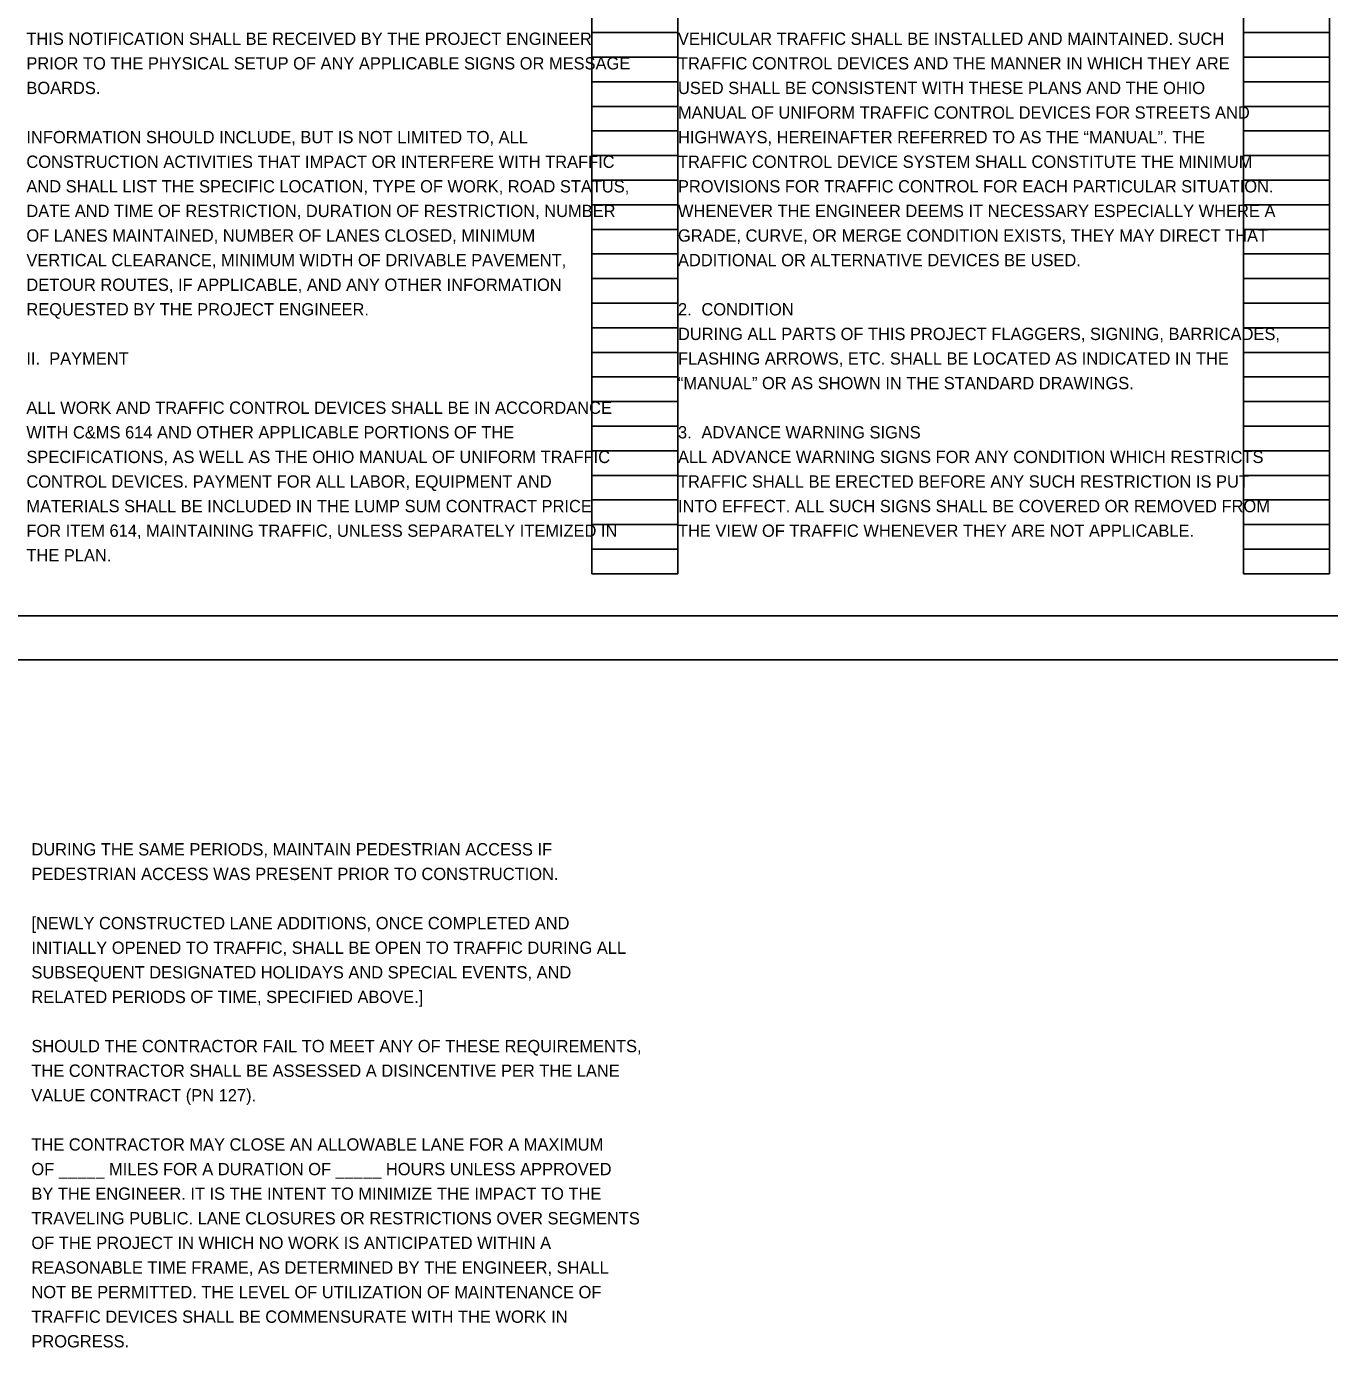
# Model space of a CAD drawing. Extents: x -15.1 to 34, y -7.8 to 43.8.
# Drawn here: x 2.4 to 17.24, y -7.83 to 7.21 of the extents above; entities that cross this region are included whole.
import ezdxf

# ---------------------------------------------------------------- set-up
doc = ezdxf.new("R2010")
doc.units = 0
for name, color, linetype in [('SH_Border', 7, 'Continuous'), ('SH_Cut_Line', 7, 'Continuous'), ('SH_Data', 7, 'Continuous'), ('SH_Text', 7, 'Continuous'), ('SN_X_Public', 7, 'Continuous')]:
    doc.layers.add(name, color=color, linetype=linetype)

msp = doc.modelspace()

# ---------------------------------------------------------------- linework, layer by layer
at = {"layer": 'SH_Border'}
msp.add_lwpolyline([(1.5, 21.5), (33.5, 21.5), (33.5, 0.5), (1.5, 0.5)], close=True, dxfattribs=at)
at = {"layer": 'SH_Cut_Line'}
msp.add_lwpolyline([(0, 0), (34, 0), (34, 22), (0, 22)], close=True, dxfattribs=at)
at = {"layer": 'SH_Data'}
for p, q in [((8.84, 0.98), (8.84, 21.14)), ((9.82, 0.98), (9.82, 21.14)), ((16.26, 0.98), (16.26, 21.14)), ((17.24, 0.98), (17.24, 21.14)), ((8.84, 7.14), (9.82, 7.14)), ((16.26, 7.14), (17.24, 7.14)), ((8.84, 6.86), (9.82, 6.86)), ((16.26, 6.86), (17.24, 6.86)), ((8.84, 6.58), (9.82, 6.58)), ((16.26, 6.58), (17.24, 6.58)), ((8.84, 6.3), (9.82, 6.3)), ((16.26, 6.3), (17.24, 6.3)), ((8.84, 6.02), (9.82, 6.02)), ((16.26, 6.02), (17.24, 6.02)), ((8.84, 5.74), (9.82, 5.74)), ((16.26, 5.74), (17.24, 5.74)), ((8.84, 5.46), (9.82, 5.46)), ((16.26, 5.46), (17.24, 5.46)), ((8.84, 5.18), (9.82, 5.18)), ((16.26, 5.18), (17.24, 5.18)), ((8.84, 4.9), (9.82, 4.9)), ((16.26, 4.9), (17.24, 4.9)), ((8.84, 4.62), (9.82, 4.62)), ((16.26, 4.62), (17.24, 4.62)), ((8.84, 4.34), (9.82, 4.34)), ((16.26, 4.34), (17.24, 4.34)), ((8.84, 4.06), (9.82, 4.06)), ((16.26, 4.06), (17.24, 4.06)), ((8.84, 3.78), (9.82, 3.78)), ((16.26, 3.78), (17.24, 3.78)), ((8.84, 3.5), (9.82, 3.5)), ((16.26, 3.5), (17.24, 3.5)), ((8.84, 3.22), (9.82, 3.22)), ((16.26, 3.22), (17.24, 3.22)), ((8.84, 2.94), (9.82, 2.94)), ((16.26, 2.94), (17.24, 2.94)), ((8.84, 2.66), (9.82, 2.66)), ((16.26, 2.66), (17.24, 2.66)), ((8.84, 2.38), (9.82, 2.38)), ((16.26, 2.38), (17.24, 2.38)), ((8.84, 2.1), (9.82, 2.1)), ((16.26, 2.1), (17.24, 2.1)), ((8.84, 1.82), (9.82, 1.82)), ((16.26, 1.82), (17.24, 1.82)), ((8.84, 1.54), (9.82, 1.54)), ((16.26, 1.54), (17.24, 1.54)), ((8.84, 1.26), (9.82, 1.26)), ((16.26, 1.26), (17.24, 1.26)), ((8.84, 0.98), (9.82, 0.98)), ((16.26, 0.98), (17.24, 0.98))]:
    msp.add_line(p, q, dxfattribs=at)

# ---------------------------------------------------------------- texts
at = {"layer": 'SH_Text'}
for s, p in [('THIS NOTIFICATION SHALL BE RECEIVED BY THE PROJECT ENGINEER ', (2.4, 7)), ('VEHICULAR TRAFFIC SHALL BE INSTALLED AND MAINTAINED. SUCH ', (9.82, 7)), ('PRIOR TO THE PHYSICAL SETUP OF ANY APPLICABLE SIGNS OR MESSAGE ', (2.4, 6.72)), ('TRAFFIC CONTROL DEVICES AND THE MANNER IN WHICH THEY ARE ', (9.82, 6.72)), ('BOARDS.', (2.4, 6.44)), ('USED SHALL BE CONSISTENT WITH THESE PLANS AND THE OHIO ', (9.82, 6.44)), ('MANUAL OF UNIFORM TRAFFIC CONTROL DEVICES FOR STREETS AND ', (9.82, 6.16)), ('INFORMATION SHOULD INCLUDE, BUT IS NOT LIMITED TO, ALL ', (2.4, 5.88)), ('HIGHWAYS, HEREINAFTER REFERRED TO AS THE “MANUAL”. THE ', (9.82, 5.88)), ('CONSTRUCTION ACTIVITIES THAT IMPACT OR INTERFERE WITH TRAFFIC', (2.4, 5.6)), ('TRAFFIC CONTROL DEVICE SYSTEM SHALL CONSTITUTE THE MINIMUM ', (9.82, 5.6)), ('AND SHALL LIST THE SPECIFIC LOCATION, TYPE OF WORK, ROAD STATUS, ', (2.4, 5.32)), ('PROVISIONS FOR TRAFFIC CONTROL FOR EACH PARTICULAR SITUATION. ', (9.82, 5.32)), ('DATE AND TIME OF RESTRICTION, DURATION OF RESTRICTION, NUMBER', (2.4, 5.04)), ('WHENEVER THE ENGINEER DEEMS IT NECESSARY ESPECIALLY WHERE A ', (9.82, 5.04)), ('OF LANES MAINTAINED, NUMBER OF LANES CLOSED, MINIMUM ', (2.4, 4.76)), ('GRADE, CURVE, OR MERGE CONDITION EXISTS, THEY MAY DIRECT THAT ', (9.82, 4.76)), ('VERTICAL CLEARANCE, MINIMUM WIDTH OF DRIVABLE PAVEMENT,', (2.4, 4.48)), ('ADDITIONAL OR ALTERNATIVE DEVICES BE USED. ', (9.82, 4.48)), ('DETOUR ROUTES, IF APPLICABLE, AND ANY OTHER INFORMATION ', (2.4, 4.2)), ('REQUESTED BY THE PROJECT ENGINEER.', (2.4, 3.92)), ('2.  ', (9.82, 3.92)), ('CONDITION', (10.087, 3.92)), ('DURING ALL PARTS OF THIS PROJECT FLAGGERS, SIGNING, BARRICADES, ', (9.82, 3.64)), ('II.  PAYMENT', (2.4, 3.36)), ('FLASHING ARROWS, ETC. SHALL BE LOCATED AS INDICATED IN THE ', (9.82, 3.36)), ('“MANUAL” OR AS SHOWN IN THE STANDARD DRAWINGS.', (9.82, 3.08)), ('ALL WORK AND TRAFFIC CONTROL DEVICES SHALL BE IN ACCORDANCE ', (2.4, 2.8)), ('WITH C&MS 614 AND OTHER APPLICABLE PORTIONS OF THE ', (2.4, 2.52)), ('3.  ', (9.82, 2.52)), ('ADVANCE WARNING SIGNS', (10.087, 2.52)), ('SPECIFICATIONS, AS WELL AS THE OHIO MANUAL OF UNIFORM TRAFFIC ', (2.4, 2.24)), ('ALL ADVANCE WARNING SIGNS FOR ANY CONDITION WHICH RESTRICTS ', (9.82, 2.24)), ('CONTROL DEVICES. PAYMENT FOR ALL LABOR, EQUIPMENT AND ', (2.4, 1.96)), ('TRAFFIC SHALL BE ERECTED BEFORE ANY SUCH RESTRICTION IS PUT ', (9.82, 1.96)), ('MATERIALS SHALL BE INCLUDED IN THE LUMP SUM CONTRACT PRICE ', (2.4, 1.68)), ('INTO EFFECT. ALL SUCH SIGNS SHALL BE COVERED OR REMOVED FROM ', (9.82, 1.68)), ('FOR ITEM 614, MAINTAINING TRAFFIC, UNLESS SEPARATELY ITEMIZED IN ', (2.4, 1.4)), ('THE VIEW OF TRAFFIC WHENEVER THEY ARE NOT APPLICABLE.', (9.82, 1.4)), ('THE PLAN.', (2.4, 1.12))]:
    msp.add_text(s, height=0.14, dxfattribs=at).set_placement(p)
at = {"layer": 'SN_X_Public'}
for s, p in [('DURING THE SAME PERIODS, MAINTAIN PEDESTRIAN ACCESS IF', (2.457, -2.227)), ('PEDESTRIAN ACCESS WAS PRESENT PRIOR TO CONSTRUCTION.', (2.457, -2.507)), ('[NEWLY CONSTRUCTED LANE ADDITIONS, ONCE COMPLETED AND ', (2.457, -3.067)), ('INITIALLY OPENED TO TRAFFIC, SHALL BE OPEN TO TRAFFIC DURING ALL ', (2.457, -3.347)), ('SUBSEQUENT DESIGNATED HOLIDAYS AND SPECIAL EVENTS, AND', (2.457, -3.627)), ('RELATED PERIODS OF TIME, SPECIFIED ABOVE.]', (2.457, -3.907)), ('SHOULD THE CONTRACTOR FAIL TO MEET ANY OF THESE REQUIREMENTS,', (2.457, -4.467)), ('THE CONTRACTOR SHALL BE ASSESSED A DISINCENTIVE PER THE LANE', (2.457, -4.747)), ('VALUE CONTRACT (PN 127).', (2.457, -5.027)), ('THE CONTRACTOR MAY CLOSE AN ALLOWABLE LANE FOR A MAXIMUM ', (2.457, -5.587)), ('OF _____ MILES FOR A DURATION OF _____ HOURS UNLESS APPROVED ', (2.457, -5.867)), ('BY THE ENGINEER. IT IS THE INTENT TO MINIMIZE THE IMPACT TO THE ', (2.457, -6.147)), ('TRAVELING PUBLIC. LANE CLOSURES OR RESTRICTIONS OVER SEGMENTS ', (2.457, -6.427)), ('OF THE PROJECT IN WHICH NO WORK IS ANTICIPATED WITHIN A ', (2.457, -6.707)), ('REASONABLE TIME FRAME, AS DETERMINED BY THE ENGINEER, SHALL ', (2.457, -6.987)), ('NOT BE PERMITTED. THE LEVEL OF UTILIZATION OF MAINTENANCE OF ', (2.457, -7.267)), ('TRAFFIC DEVICES SHALL BE COMMENSURATE WITH THE WORK IN ', (2.457, -7.547)), ('PROGRESS.', (2.457, -7.827))]:
    msp.add_text(s, height=0.14, dxfattribs=at).set_placement(p)

doc.saveas('drawing.dxf')
